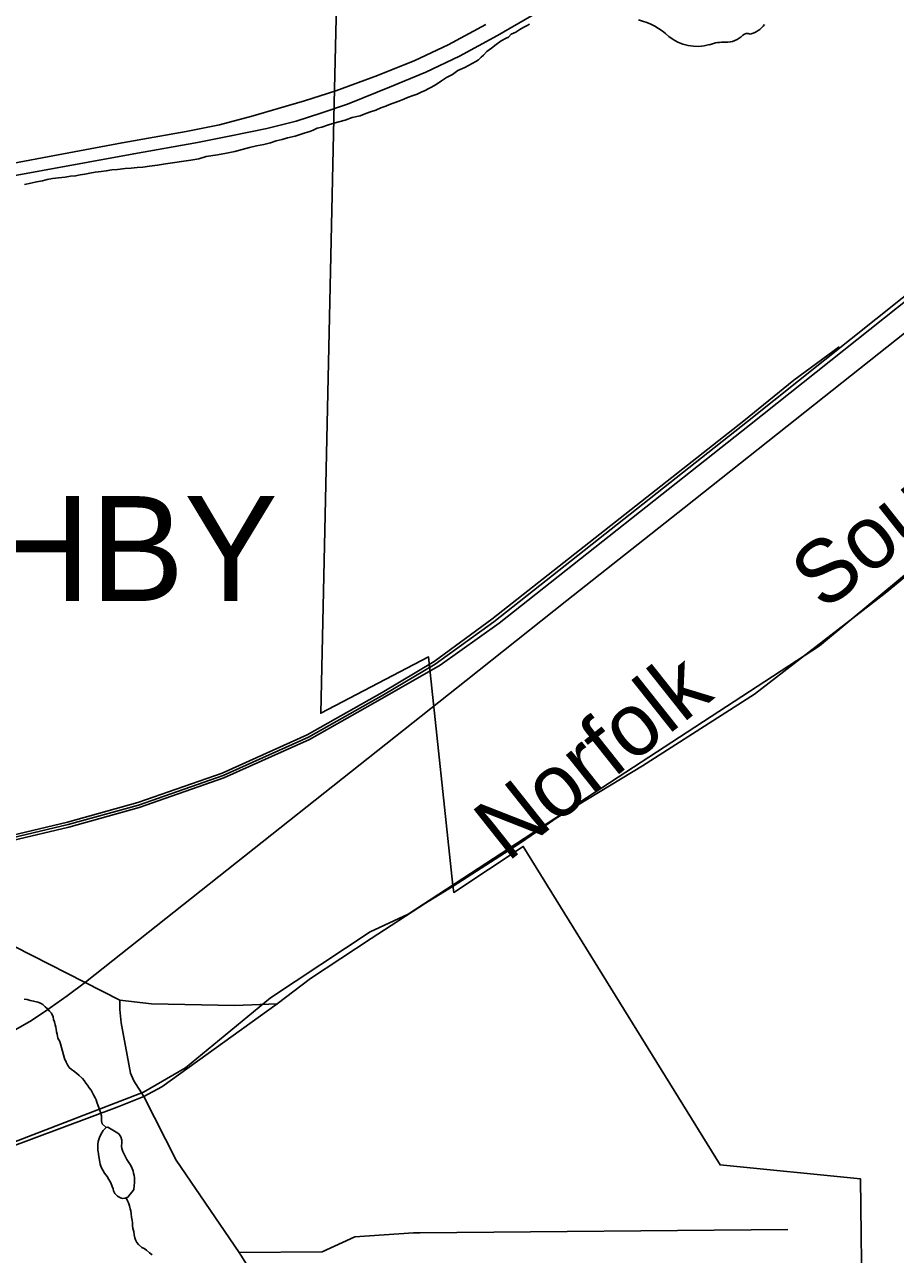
# Model space of a CAD drawing. Extents: x 0 to 34, y 0 to 22.
# Drawn here: x 6.635 to 7.421, y 14.779 to 15.889 of the extents above; entities that cross this region are included whole.
import ezdxf

# ---------------------------------------------------------------- set-up
doc = ezdxf.new("R2010")
doc.units = 0
for name, color, linetype in [('GM_X_City_Street', 7, 'Continuous'), ('GM_X_Corporation', 7, 'Continuous'), ('GM_X_Corporation_Text', 7, 'Continuous'), ('GM_X_County_Road', 7, 'Continuous'), ('GM_X_Minor_Lake', 7, 'Continuous'), ('GM_X_Minor_River', 7, 'Continuous'), ('GM_X_Rail_Line', 7, 'Continuous'), ('GM_X_Rail_Line_Text', 7, 'Continuous'), ('GM_X_State_Route', 7, 'Continuous'), ('GM_X_State_Shield', 7, 'Continuous'), ('GM_X_US_Route', 7, 'Continuous')]:
    doc.layers.add(name, color=color, linetype=linetype)

msp = doc.modelspace()

# ---------------------------------------------------------------- linework, layer by layer
at = {"layer": 'GM_X_City_Street'}
for points in [[(6.7208, 15.0088), (6.7495, 15.0054), (6.8248, 15.0039), (6.863, 15.0056)], [(6.8285, 14.7811), (6.9036, 14.7816), (6.9328, 14.7951), (6.9859, 14.7988), (6.9918, 14.7989), (7.3235, 14.8019)]]:
    msp.add_lwpolyline(points, dxfattribs=at)
at = {"layer": 'GM_X_Corporation'}
for points in [[(6.9579, 18.132), (6.9502, 17.5872), (6.9468, 17.2888), (6.9413, 17.0038), (6.9287, 16.435), (6.9142, 15.8181), (6.9021, 15.2678), (6.9994, 15.3186), (7.0214, 15.1124), (7.0221, 15.106), (7.0848, 15.1475), (7.2625, 14.8601), (7.3892, 14.8475), (7.3905, 14.7219), (7.3907, 14.701), (7.7494, 14.7173), (7.8563, 14.7146), (7.8592, 14.6786), (7.9049, 14.6645), (8.8347, 14.6937), (8.9001, 14.6961), (8.9001, 19.9513)], [(7.3905, 14.7219), (7.3892, 14.8475), (7.2625, 14.8601), (7.0848, 15.1475), (7.0221, 15.106), (7.0214, 15.1124), (6.9994, 15.3186), (6.9021, 15.2678), (6.9142, 15.8181), (6.9287, 16.435), (6.9413, 17.0038), (6.9468, 17.2888), (6.9502, 17.5872), (6.9579, 18.132)]]:
    msp.add_lwpolyline(points, dxfattribs=at)
at = {"layer": 'GM_X_County_Road'}
msp.add_line((6.5949, 15.0728), (6.7208, 15.0088), dxfattribs=at)
for points in [[(6.7208, 15.0088), (6.721, 15.0005), (6.7222, 14.9884), (6.7305, 14.9428), (6.7334, 14.9361), (6.7426, 14.922)], [(6.7426, 14.922), (6.7716, 14.8644), (6.8285, 14.7811), (6.8301, 14.7786), (6.8736, 14.7096), (6.8879, 14.6955), (6.9139, 14.6797), (6.9659, 14.6487)]]:
    msp.add_lwpolyline(points, dxfattribs=at)
at = {"layer": 'GM_X_Minor_Lake'}
for points in [[(6.71, 14.8941), (6.7085, 14.8938), (6.7059, 14.8911), (6.7037, 14.8877), (6.7026, 14.885), (6.7015, 14.8812), (6.7011, 14.8785), (6.7012, 14.8755), (6.7012, 14.8736), (6.7016, 14.8705), (6.7017, 14.8694)], [(6.7017, 14.8694), (6.7028, 14.8626), (6.7032, 14.8607), (6.704, 14.858), (6.7071, 14.8527), (6.7094, 14.8497), (6.711, 14.847), (6.7129, 14.844), (6.7141, 14.8406), (6.7149, 14.8387), (6.7153, 14.8368), (6.7164, 14.8345), (6.7187, 14.8319), (6.7214, 14.8304), (6.7233, 14.8297), (6.7256, 14.8301), (6.7282, 14.8309), (6.7301, 14.8339), (6.732, 14.8358), (6.7335, 14.8381), (6.7338, 14.8412), (6.7342, 14.8442), (6.7341, 14.8465), (6.7341, 14.8488), (6.7337, 14.8507), (6.7333, 14.8526), (6.7329, 14.8545), (6.7317, 14.8579), (6.7302, 14.8605), (6.7283, 14.8632), (6.7271, 14.8651), (6.7236, 14.8723), (6.7228, 14.8749), (6.7224, 14.8772), (6.7227, 14.8802), (6.7227, 14.8825), (6.7219, 14.8856), (6.72, 14.8882), (6.7177, 14.8897), (6.71, 14.8941)]]:
    msp.add_lwpolyline(points, dxfattribs=at)
at = {"layer": 'GM_X_Minor_River'}
for points in [[(6.9472, 15.8105), (6.9518, 15.8121), (6.9563, 15.814), (6.9608, 15.8156), (6.9642, 15.8171), (6.9684, 15.8187), (6.9725, 15.8202), (6.9771, 15.8218), (6.9805, 15.8234), (6.9854, 15.8253), (6.9892, 15.8265), (6.9929, 15.8281), (6.9963, 15.8296), (6.999, 15.8312), (7.0016, 15.8323), (7.0043, 15.8339), (7.0073, 15.8358), (7.011, 15.8385), (7.0156, 15.8416), (7.0209, 15.8443), (7.0257, 15.8478), (7.0322, 15.8505), (7.042, 15.8559), (7.0446, 15.8575), (7.0469, 15.8598), (7.0491, 15.8617), (7.0521, 15.8648), (7.0563, 15.8679), (7.0604, 15.8713), (7.0649, 15.8744), (7.0694, 15.8771), (7.0717, 15.8779), (7.074, 15.8806), (7.0781, 15.8825), (7.0819, 15.8849), (7.0853, 15.8868), (7.0883, 15.8883), (7.0906, 15.8895)], [(6.6348, 15.745), (6.6405, 15.7462), (6.6458, 15.7474), (6.6511, 15.7482), (6.6553, 15.7494), (6.6602, 15.7502), (6.6655, 15.751), (6.6716, 15.7515), (6.6765, 15.7523), (6.681, 15.7527), (6.6852, 15.7535), (6.6894, 15.7543), (6.6939, 15.7551), (6.6988, 15.7559), (6.7041, 15.7567), (6.7087, 15.7571), (6.7136, 15.758), (6.7189, 15.7584), (6.7257, 15.7592), (6.7311, 15.7597), (6.7364, 15.7601), (6.7417, 15.7605), (6.7477, 15.7613), (6.7549, 15.7622), (6.7621, 15.7634), (6.7849, 15.767), (6.7921, 15.7682), (6.7989, 15.7702), (6.8091, 15.7718), (6.8171, 15.7731), (6.8246, 15.7747), (6.8314, 15.7766), (6.8379, 15.7782), (6.8443, 15.7798), (6.8508, 15.781), (6.8568, 15.7826), (6.8621, 15.7842), (6.8674, 15.7854), (6.8723, 15.7869), (6.8791, 15.7885), (6.8837, 15.7901), (6.8882, 15.7916), (6.8924, 15.7928), (6.8954, 15.794), (6.8988, 15.7956), (6.9033, 15.7967), (6.9083, 15.7983), (6.9132, 15.7999), (6.9185, 15.8015), (6.9241, 15.803), (6.9306, 15.8054), (6.9378, 15.807), (6.9427, 15.8089), (6.9472, 15.8105)], [(6.6347, 15.0098), (6.6374, 15.0095), (6.6401, 15.0084), (6.6431, 15.008), (6.6469, 15.0069), (6.6492, 15.0062), (6.6515, 15.005), (6.6534, 15.0028), (6.6557, 15.0009), (6.6576, 14.999), (6.6592, 14.9971), (6.6607, 14.9937), (6.6611, 14.9915), (6.6619, 14.9892), (6.6627, 14.9865), (6.6631, 14.9846), (6.6635, 14.9827), (6.6639, 14.9801), (6.6643, 14.9782), (6.6647, 14.9763), (6.6651, 14.9744), (6.6667, 14.9714), (6.6675, 14.9695), (6.6683, 14.966)], [(6.6683, 14.966), (6.671, 14.9562), (6.6726, 14.9528), (6.6737, 14.9505), (6.6753, 14.9482), (6.6772, 14.9464), (6.6791, 14.9449), (6.6818, 14.943), (6.6841, 14.9407), (6.6872, 14.9381), (6.6887, 14.9362), (6.6903, 14.9339), (6.6918, 14.932), (6.6933, 14.9298), (6.6949, 14.9275), (6.6964, 14.9252), (6.6972, 14.9234), (6.6988, 14.9207), (6.6995, 14.9188), (6.7003, 14.9169), (6.7015, 14.9135), (6.7027, 14.9105), (6.7035, 14.9074), (6.7043, 14.9044), (6.7043, 14.9025), (6.7043, 14.8998), (6.7051, 14.8972), (6.7085, 14.8938)], [(6.7266, 14.8304), (6.7279, 14.8278), (6.7287, 14.8259), (6.7295, 14.8233), (6.7302, 14.8206), (6.7307, 14.8187), (6.7311, 14.8161), (6.7315, 14.813), (6.7319, 14.81), (6.7323, 14.8081), (6.7323, 14.8054), (6.7327, 14.8028), (6.7335, 14.8001), (6.7339, 14.7971), (6.7343, 14.7944), (6.7351, 14.7925), (6.7363, 14.7902), (6.7378, 14.7884), (6.7409, 14.7857), (6.7428, 14.7846), (6.7451, 14.7831), (6.7478, 14.7809), (6.7501, 14.779)]]:
    msp.add_lwpolyline(points, dxfattribs=at)
at = {"layer": 'GM_X_Rail_Line'}
for points in [[(6.6237, 15.1553), (6.6743, 15.1672), (6.7378, 15.1849), (6.814, 15.2116), (6.891, 15.2462), (6.9588, 15.2844), (7.0054, 15.3121), (7.0582, 15.3501), (7.2871, 15.5311), (7.6599, 15.8282), (8.0769, 16.1566), (8.5157, 16.5045), (8.8904, 16.7977), (8.9001, 16.8054)], [(6.6242, 15.153), (6.6748, 15.1649), (6.7385, 15.1827), (6.8148, 15.2095), (6.8921, 15.2442), (6.96, 15.2825), (7.0098, 15.3111), (7.0632, 15.3489), (7.289, 15.5277), (7.6646, 15.8264), (8.083, 16.1569), (8.5171, 16.5027), (8.8918, 16.7959), (8.9001, 16.8025)], [(6.6266, 14.9819), (6.6396, 14.9896), (6.6528, 14.9982), (6.6734, 15.0126), (6.6898, 15.0251), (7.0335, 15.2973), (7.1242, 15.3694), (7.23, 15.4532), (7.3475, 15.5463), (7.4216, 15.6051), (7.5158, 15.6797), (7.6294, 15.7697), (7.7359, 15.8545), (8.0929, 16.1372), (8.3833, 16.3675), (8.7147, 16.6305), (8.9001, 16.7773)], [(8.9001, 16.2761), (8.2846, 16.0525), (8.2351, 16.0308), (7.6286, 15.5585), (7.3522, 15.3285), (6.9809, 15.0864), (6.9468, 15.0706), (6.8568, 15.011), (6.7801, 14.9477), (6.7423, 14.9258), (6.4831, 14.826), (6.4161, 14.8066), (6.3197, 14.7585), (6.2075, 14.6898), (6.1801, 14.6771), (6.15, 14.6743), (6.1143, 14.6764), (6.1057, 14.6241), (6.068, 14.5413), (6.0488, 14.5029)], [(6.6233, 15.1575), (6.6737, 15.1694), (6.7371, 15.1871), (6.8131, 15.2138), (6.89, 15.2483), (6.9575, 15.2864), (7.0046, 15.3145), (7.0566, 15.3526), (7.2838, 15.5315), (7.3291, 15.5683), (7.37, 15.5985)]]:
    msp.add_lwpolyline(points, dxfattribs=at)
at = {"layer": 'GM_X_State_Route'}
for points in [[(6.9254, 15.8172), (6.9293, 15.8185), (6.9642, 15.8326), (6.9969, 15.8462), (7.0274, 15.8608), (7.0616, 15.8793), (7.0924, 15.897), (7.1268, 15.9189), (7.1549, 15.9384), (7.1785, 15.9571), (7.198, 15.9734), (7.2182, 15.9909), (7.2437, 16.0148), (7.311, 16.0857), (7.3604, 16.1376), (7.4183, 16.2007), (7.5413, 16.3341)], [(6.5624, 15.7523), (6.723, 15.7826), (6.7807, 15.7928), (6.8107, 15.7987), (6.8413, 15.807), (6.8639, 15.8135), (6.8875, 15.8205), (6.9157, 15.8295), (6.9535, 15.8433), (6.9871, 15.8569), (7.017, 15.8708), (7.0512, 15.8892)], [(6.0172, 15.5686), (6.0458, 15.5871), (6.0753, 15.6041), (6.1061, 15.6213), (6.1247, 15.6298), (6.1629, 15.6475), (6.1946, 15.6601), (6.2414, 15.6756), (6.2772, 15.6867), (6.3106, 15.6951), (6.3484, 15.703), (6.4011, 15.7126), (6.4757, 15.7246), (6.565, 15.7419), (6.7334, 15.7726), (6.7911, 15.7828), (6.8211, 15.7888), (6.8534, 15.7955), (6.8799, 15.8022), (6.9031, 15.8095), (6.9254, 15.8172)]]:
    msp.add_lwpolyline(points, dxfattribs=at)
at = {"layer": 'GM_X_State_Shield'}
for centre, radius, start, end in [((7.1733, 15.8322), 0.0632, 47.1842, 75.836), ((7.2845, 15.9027), 0.0226, 282.8732, 323.2771), ((7.2416, 15.9096), 0.0401, 230.7004, 286.2918), ((7.2648, 15.8404), 0.0329, 85.6951, 111.2099), ((7.2677, 15.8946), 0.0214, 268.777, 315.5493), ((7.287, 15.8752), 0.00601, 65.7517, 132.6484)]:
    msp.add_arc(centre, radius, start, end, dxfattribs=at)
at = {"layer": 'GM_X_US_Route'}
for points in [[(7.1055, 15.1667), (7.1145, 15.173), (7.1925, 15.2203), (7.2935, 15.285), (7.4113, 15.3762), (7.5045, 15.4529), (7.5832, 15.5158)], [(7.0723, 15.1442), (7.0825, 15.1507), (7.1055, 15.1667)], [(7.0044, 15.1011), (7.0216, 15.1118), (7.0723, 15.1442)], [(6.5664, 14.8555), (6.5683, 14.8562), (6.7185, 14.9123), (6.7426, 14.922), (6.7587, 14.9307), (6.863, 15.0056), (6.8928, 15.0283), (6.9478, 15.0646), (6.9967, 15.0963), (7.0044, 15.1011)]]:
    msp.add_lwpolyline(points, dxfattribs=at)

# ---------------------------------------------------------------- texts
at = {"layer": 'GM_X_Corporation_Text'}
msp.add_text('WILLOUGHBY', height=0.0947, rotation=0, dxfattribs=at).set_placement((6.019, 15.369))
at = {"layer": 'GM_X_Rail_Line_Text'}
for s, rotation, p in [('Southern', 38.3763, (7.356, 15.3591)), ('Norfolk', 38.4568, (7.0705, 15.1327))]:
    msp.add_text(s, height=0.05663, rotation=rotation, dxfattribs=at).set_placement(p)

doc.saveas('drawing.dxf')
